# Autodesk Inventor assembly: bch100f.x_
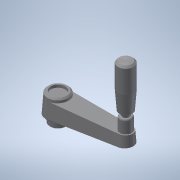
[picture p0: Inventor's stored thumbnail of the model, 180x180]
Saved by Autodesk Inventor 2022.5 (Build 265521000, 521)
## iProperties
Part Number: bch100f.x_
Material: 一般
Document SubType Name: Assembly
Designer: ImaoCorp
Sending System: SOLIDWORKS 2017-2017317
MC: AMD64
MC_MODEL: Intel64 Family 6 Model 60 Stepping 3, GenuineIntel
OS: Windows_NT
FRU: Parasolid Version 29.0, build 201,  4-17-2017
FORMAT: text
GUISE: transmit
KEY: bch100f
FILE: bch100f.x_t
DATE: Fri Mar 15 10:34:01 2019
Author: ImaoCorp
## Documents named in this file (3)
- X:\14_SW2022-Inv2022\00_全2023-1023新製品(TCC)まで\b\bch100f\BCH100F.iam
- X:\14_SW2022-Inv2022\00_全2023-1023新製品(TCC)まで\b\bch100f\bch100f_01.ipt
- X:\14_SW2022-Inv2022\00_全2023-1023新製品(TCC)まで\b\bch100f\bch100f_02.ipt
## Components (2 placed, 2 different names)
1. bch100f_01
2. bch100f_02
